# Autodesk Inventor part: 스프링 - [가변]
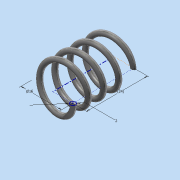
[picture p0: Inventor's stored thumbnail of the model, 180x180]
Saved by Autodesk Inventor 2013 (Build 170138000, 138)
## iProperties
Created: 2015-09
Part Number: 스프링 - [가변]
Material: 강철, 탄소
Document SubType Name: Modeling
Designer: WINDOWS7
Mass: 4.92096 g
Surface Area: 12.7475 cm^2
Volume: 0.625281 cm^3
Density: 7.87 g/cm^3
Author: WINDOWS7
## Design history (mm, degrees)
sketch "스케치1"
  geometry: L1 (0, 0)-(8, 0); L2 (8, 0)-(8, 42); L3 (8, 42)-(0, 42); L4 (0, 42)-(0, 0); C1 r 1 at (8, 0)
  constraints: 8 end point, 2 parallel, 1 centre point, 1 coincident, 1 horizontal, 1 perpendicular
  dimensions: "d0" = 2 diameter of C1; "d2" = 16 diameter of L2 L4; "d3" = 42 distance between parallel lines of L1 L3 (derived)
feature "코일1" pitch "d4" = 10; turns "d6" = 4; dims "d5" = 42 (= d3), "d7" = 0, angle "d8" = 90 deg, angle "d9" = 90 deg, "d10" = 0, "d11" = 0
node "작업 평면1"
node "작업 평면2"
sketch "스케치2"
  geometry: L1 (0, 0)-(2, 0) reference; 1 further point
  constraints: 1 horizontal alignment
  node "절단 모서리 투영1"
sketch "스케치3"
  geometry: L1 (2, 0)-(0, 0) reference; 1 further point
  constraints: 1 horizontal alignment
  node "절단 모서리 투영2"
extrude "돌출1" cut sketch "스케치2" distance "d12" = 10; taper "d13" = 0 deg
extrude "돌출2" cut sketch "스케치3" distance "d14" = 10; taper "d15" = 0 deg
node "솔리드1"
